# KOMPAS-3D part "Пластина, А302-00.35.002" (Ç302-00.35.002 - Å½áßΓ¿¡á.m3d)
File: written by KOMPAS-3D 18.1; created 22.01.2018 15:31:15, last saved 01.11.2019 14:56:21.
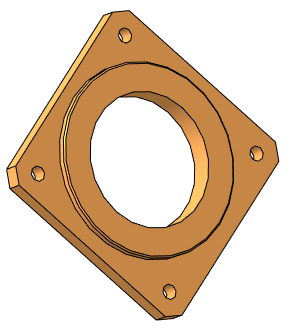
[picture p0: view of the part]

Document properties: Автор: Милов; Полное имя файла: D:\Мембранные насосы\Мембранный электропривод\А302-00.00.000 - ASTRA-302 (МЭ200)\3Д\А302-00.35.002 - Пластина.m3d

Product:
- Part/product: Пластина  | designation А302-00.35.002
    Масса: 0.697075
    Раздел спецификации: Детали
    Форматы листов документа: A4
  - Component: Пластина  | designation А302-00.35.002  | Масса: 0.7; Раздел спецификации: Детали; Форматы листов документа: A4
- Part/product: Пластина  | designation А302-04.35.002
    Масса: 1.19076
    Раздел спецификации: Детали
    Форматы листов документа: A4
- Part/product: Пластина  | designation А302-05.35.002
    Масса: 0.658749
    Раздел спецификации: Детали
    Форматы листов документа: A4
- Part/product: Пластина  | designation А302-00.35.002-01
    Масса: 1.44135
    Раздел спецификации: Детали
    Форматы листов документа: A4

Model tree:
1. Эскиз:1
2. Операция выдавливания:3
     Расстояние 1 = 5
3. Фаска:1  (with: Операция выдавливания:3)  (labels: ..\3Д ПВХ\Отработка\А302-01.20.000 - Мотор-редуктор.a3d)
     Угол = 45; Длина 1 = 8; Длина 2 = 8
4. Эскиз:7  (with: Операция выдавливания:3, Фаска:1, Операция без истории:1)  (labels: FB 063)
5. Элемент выдавливания:2
     Расстояние 2 = 8
6. Эскиз:9  (with: Элемент выдавливания:2)
7. Элемент выдавливания:3
     Расстояние 2 = 7
8. Эскиз:13  (with: Операция выдавливания:3)
9. Элемент выдавливания:4
     Расстояние 2 = 15
10. Фаска:4  (with: Элемент выдавливания:2)
     Угол = 45; Длина 1 = 1; Длина 2 = 1
11. Элемент выдавливания:12  (with: Элемент выдавливания:2)  (labels: ..\3Д ПВХ\А302-01.35.000 - Фланец.a3d)
     Расстояние 1 = 3
12. Элемент выдавливания:5  (with: Операция выдавливания:3, Элемент выдавливания:1)
     Расстояние 1 = 2.5
13. Эскиз:15  (with: Операция выдавливания:3, Элемент выдавливания:6)
14. Элемент выдавливания:8  (labels: ..\3Д ПВХ\Отработка\А302-01.20.000 - Мотор-редуктор.a3d; ..\3Д ПВХ\А302-01.35.000 - Фланец.a3d)
     Расстояние 2 = 7.5

Referenced files in D:\Мембранные насосы\Мембранный электропривод\А302-00.00.000 - ASTRA-302 (МЭ200)\3Д ПВХ\Отработка\: А302-01.20.000 - Мотор-редуктор.a3d
Referenced files in D:\Мембранные насосы\Мембранный электропривод\А302-00.00.000 - ASTRA-302 (МЭ200)\3Д ПВХ\: А302-01.35.000 - Фланец.a3d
